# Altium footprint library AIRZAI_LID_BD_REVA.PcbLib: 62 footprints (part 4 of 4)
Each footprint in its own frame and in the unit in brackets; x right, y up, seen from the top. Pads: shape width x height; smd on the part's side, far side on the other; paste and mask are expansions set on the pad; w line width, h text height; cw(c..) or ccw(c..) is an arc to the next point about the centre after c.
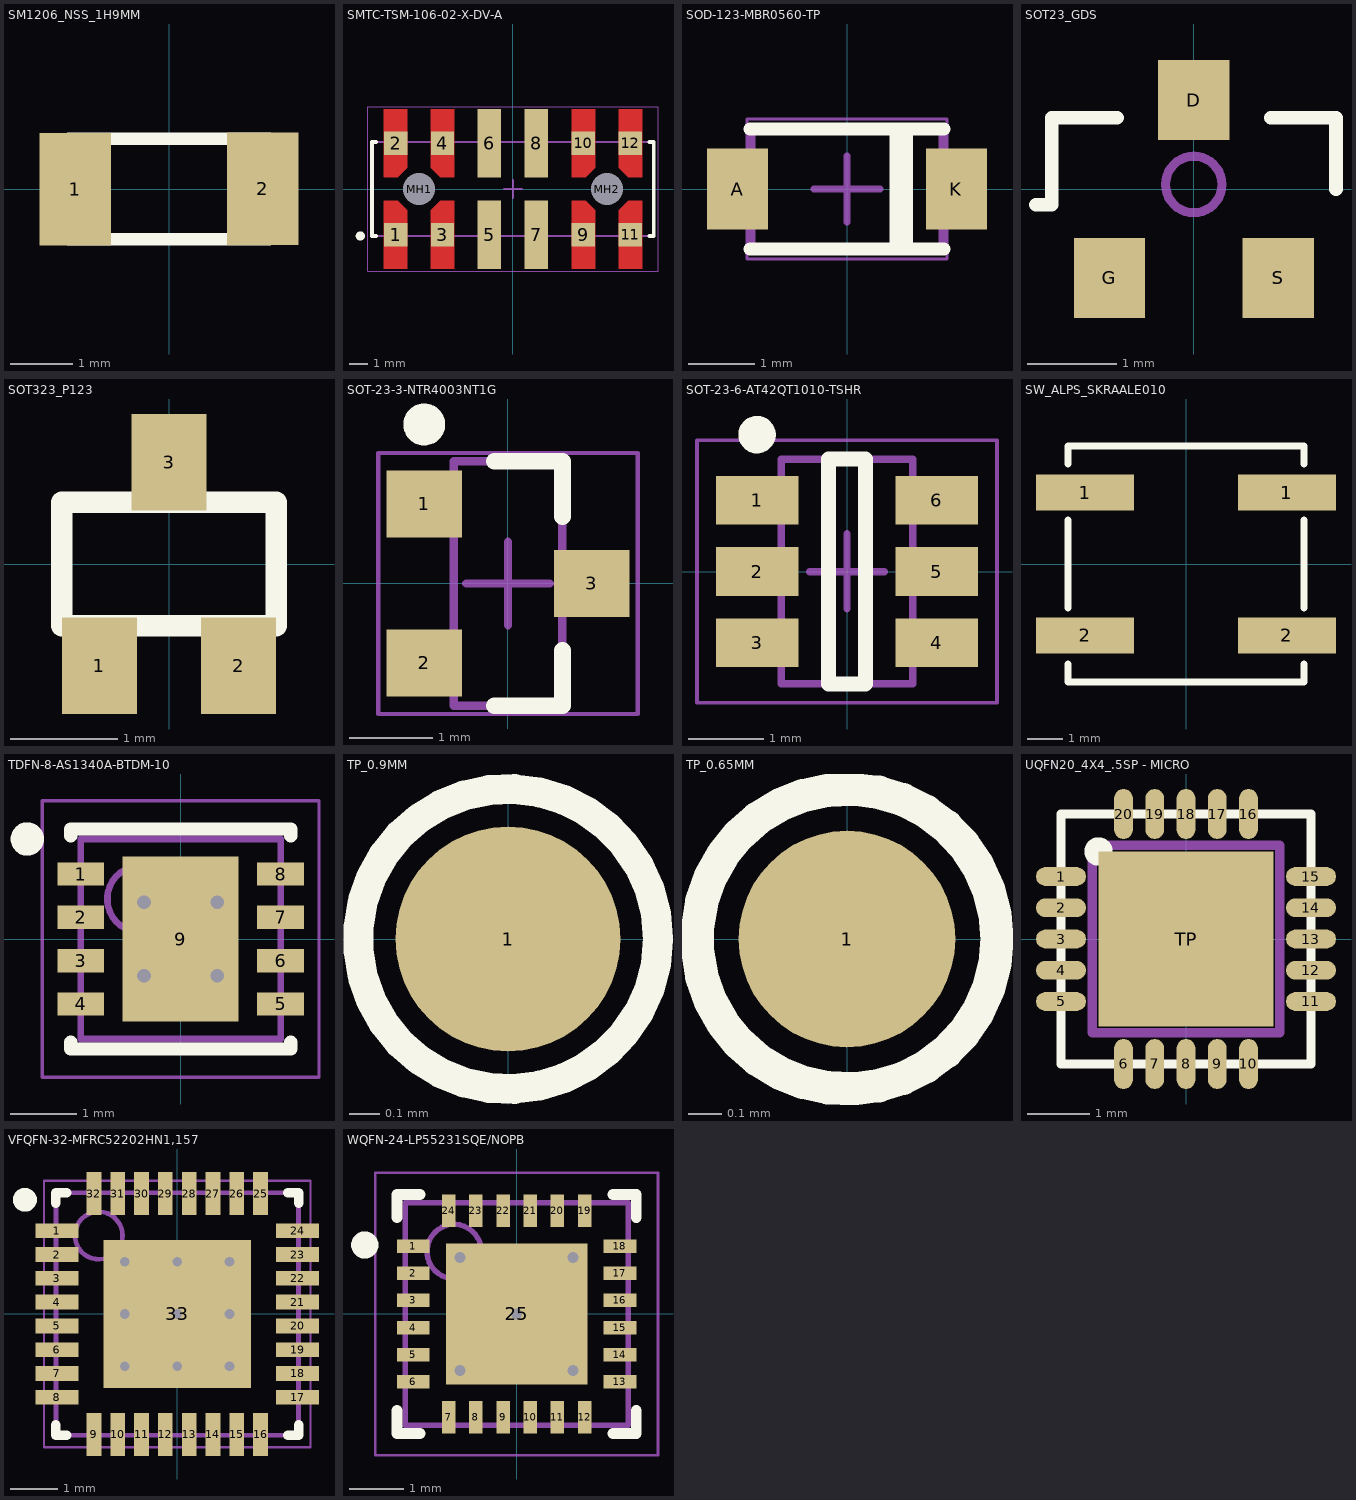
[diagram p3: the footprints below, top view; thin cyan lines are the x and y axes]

## SM1206_NSS_1H9MM [mm] "CAP_1206_1.9MM_HIGH"
height 1.9
pads (2):
  rect 1.15x1.8 smd: 1(-1.5,0) 2(1.5,0)
Top Overlay:
  lines w0.2: -1.6,-0.8 1.6,-0.8 1.6,0.8 -1.6,0.8 -1.6,-0.8
3D body: height 1.9, standoff 0, extent -1.7,-0.9 1.7,0.9

## SMTC-TSM-106-02-X-DV-A [mm] "Double Row Gullwing Asm, 2x6 Pins, Vertical, 2.54mm Pitch, Male"
height 12.19
pads (14):
  rect 1.27x1.27 smd: 1(-6.35,-2.475) 2(-6.35,2.475) 3(-3.81,-2.475) 4(-3.81,2.475) 9(3.81,-2.475) 10(3.81,2.475) 11(6.35,-2.475) 12(6.35,2.475)
  rect 1.27x3.68 smd: 5(-1.27,-2.475) 6(-1.27,2.475) 7(1.27,-2.475) 8(1.27,2.475)
  round 1.43 hole 1.73 unplated: MH1(-5.08,0) MH2(5.08,0)
Top Layer:
  region: -6.985,0.635 -6.225,0.635 -5.715,1.145 -5.715,4.315 -6.985,4.315
  region: -3.175,0.635 -3.935,0.635 -4.445,1.145 -4.445,4.315 -3.175,4.315
  region: 6.985,0.635 6.225,0.635 5.715,1.145 5.715,4.315 6.985,4.315
  region: 3.175,0.635 3.935,0.635 4.445,1.145 4.445,4.315 3.175,4.315
  region: 3.175,-0.635 3.935,-0.635 4.445,-1.145 4.445,-4.315 3.175,-4.315
  region: 6.985,-0.635 6.225,-0.635 5.715,-1.145 5.715,-4.315 6.985,-4.315
  region: -3.175,-0.635 -3.935,-0.635 -4.445,-1.145 -4.445,-4.315 -3.175,-4.315
  region: -6.985,-0.635 -6.225,-0.635 -5.715,-1.145 -5.715,-4.315 -6.985,-4.315
Top Overlay:
  circle w0.25: c-8.255,-2.54 r0.125
  lines w0.2: -7.385,-2.54 -7.62,-2.54 -7.62,2.54 -7.385,2.54 ; 7.385,-2.54 7.62,-2.54 7.62,2.54 7.385,2.54
Mechanical 13:
  lines w0.1: -7.62,-2.54 -7.62,2.54 7.62,2.54 7.62,-2.54 -7.62,-2.54
Mechanical 15:
  lines w0.05: -7.845,-4.44 -7.845,4.44 7.845,4.44 7.845,-4.44 -7.845,-4.44
  lines w0.1: -0.5,0 0.5,0 ; 0,-0.5 0,0.5
3D body "TSM-106-02-T-DV-A-TR.stp": height 11.94, standoff -1.27, extent -7.62,-3.721 7.62,3.721

## SOD-123-MBR0560-TP [mil] "SODFL, 2-Leads, Body 1.8x2.85mm, IPC Medium Density"
height 53.15
pads (2):
  rect 36x48.03 smd: A(-64.5,0) K(64.5,0)
Top Overlay:
  lines w7.8: 29,-35 29,35 ; 35,-35 35,34.43
  lines w7.87: -57.09,-35.43 57.09,-35.43 ; -57.09,35.43 57.09,35.43
Mechanical 13:
  lines w3.94: -56.1,-35.43 56.1,-35.43 56.1,35.43 -56.1,35.43 -56.1,-35.43
Mechanical 15:
  lines w1.97: -59.06,-41.34 59.06,-41.34 59.06,41.34 -59.06,41.34 -59.06,-41.34
  lines w3.94: -19.68,0 19.68,0 ; 0,-19.68 0,19.68
3D body "SW3DPS-SOD123-DEFAULT.STEP": height 52, standoff 2, extent -72.83,-31.49 72.84,31.51

## SOT23_GDS [mm]
height 1.2
pads (3):
  rect 0.8x0.9 smd: D(0,1)
  rect 0.8x0.9 smd paste-0.05 mask+0.07: G(-0.95,-1) S(0.95,-1)
Top Overlay:
  lines w0.152: -1.775,-0.175 -1.6,-0.175 -1.6,0.8 -0.864,0.8 ; 0.864,0.8 1.6,0.8 1.6,0
Mechanical 3:
  lines w0.102: -0.318,0.051 cw(c0,0.051) 0,0.368 cw(c0,0.051) 0.318,0.051 cw(c0,0.051) 0,-0.267 cw(c0,0.051) -0.318,0.051
3D body: height 1.2, standoff 0, extent -1.5,-0.7 1.5,0.7

## SOT323_P123 [mm] "123_PINS"
height 1
pads (3):
  rect 0.7x0.9 smd: 1(-0.65,-0.95) 2(0.65,-0.95) 3(0,0.95)
Top Overlay:
  lines w0.2: -1,-0.575 1,-0.575 1,0.575 -1,0.575 -1,-0.575
Mechanical 1:
  lines w0.127: -1,-0.6 -0.85,-0.6 1,-0.6 1,0.6 -1,0.6 -1,-0.6
3D body: height 0.1, standoff 0, extent 0.45,-1.1 0.85,-0.675
3D body: height 0.1, standoff 0, extent -0.85,-1.1 -0.45,-0.675
3D body: height 0.1, standoff 0, extent -0.2,0.675 0.2,1.1
3D body: height 1.1, standoff 0.1, extent -1.1,-0.675 1.1,0.675

## SOT-23-3-NTR4003NT1G [mm] "SOT23, 3-Leads, Body 2.92x1.3mm, Pitch 0.95mm"
height 1.11
pads (3):
  rect 0.9x0.8 smd: 1(-1,0.95) 2(-1,-0.95) 3(1,0)
Top Overlay:
  circle w0.25: c-1,1.9 r0.125
  lines w0.2: -0.165,-1.46 0.65,-1.46 0.65,-0.8 ; -0.165,1.46 0.65,1.46 0.65,0.8
Mechanical 13:
  lines w0.1: -0.65,-1.46 -0.65,1.46 0.65,1.46 0.65,-1.46 -0.65,-1.46
Mechanical 15:
  lines w0.05: -1.55,-1.56 -1.55,1.56 1.55,1.56 1.55,-1.56 -1.55,-1.56
  lines w0.1: -0.5,0 0.5,0 ; 0,-0.5 0,0.5
3D body: height 1.11, standoff 0.01, extent -0.65,-1.46 0.65,1.46

## SOT-23-6-AT42QT1010-TSHR [mm] "SOT23, 6-Leads, Body 2.9x1.6mm, Pitch 0.95mm, Lead Span 2.8mm, IPC Medium Density"
height 1.45
pads (6):
  rect 1.1x0.65 smd: 1(-1.2,0.95) 2(-1.2,0) 3(-1.2,-0.95) 4(1.2,-0.95) 5(1.2,0) 6(1.2,0.95)
Top Overlay:
  circle w0.25: c-1.2,1.825 r0.125
  lines w0.2: -0.25,-1.5 0.25,-1.5 0.25,1.5 -0.25,1.5 -0.25,-1.5
Mechanical 13:
  lines w0.1: -0.875,-1.5 -0.875,1.5 0.875,1.5 0.875,-1.5 -0.875,-1.5
Mechanical 15:
  lines w0.05: -2,-1.75 -2,1.75 2,1.75 2,-1.75 -2,-1.75
  lines w0.1: -0.5,0 0.5,0 ; 0,-0.5 0,0.5
3D body: height 1.45, standoff 0, extent -0.875,-1.5 0.875,1.5

## SW_ALPS_SKRAALE010 [mm] "6.2MM SQ 2.9RD ACT"
height 3.4
pads (4):
  rect 2.75x1 smd paste-0.1 mask+0.102: 1(-2.825,2) 1(2.825,2) 2(-2.825,-2) 2(2.825,-2)
Top Overlay:
  lines w0.198: -3.3,-2.8 -3.3,-3.3 3.3,-3.3 3.3,-2.8 ; -3.3,-1.233 -3.3,1.232 ; -3.3,2.8 -3.3,3.3 3.3,3.3 3.3,2.8 ; 3.3,-1.233 3.3,1.232
3D body "SKRAAL.STEP": height 3.48, standoff 0, extent -3.399,-3.215 3.399,3.215

## TDFN-8-AS1340A-BTDM-10 [mm]
height 0.8
pads (9):
  rect 0.7x0.35 smd: 1(-1.498,0.975) 2(-1.498,0.325) 3(-1.498,-0.325) 4(-1.498,-0.975) 5(1.498,-0.975) 6(1.498,-0.325) 7(1.498,0.325) 8(1.498,0.975)
  rect 1.74x2.48 smd: 9(0,0)
via -0.55,0.55 diameter 0.508 hole 0.203
via 0.55,0.55 diameter 0.508 hole 0.203
via -0.55,-0.55 diameter 0.508 hole 0.203
via 0.55,-0.55 diameter 0.508 hole 0.203
Top Overlay:
  circle w0.25: c-2.3,1.5 r0.125
  lines w0.2: -1.65,-1.55 -1.65,-1.65 0.25,-1.65 1.65,-1.65 1.65,-1.55 ; -1.65,1.55 -1.65,1.65 0.25,1.65 1.65,1.65 1.65,1.55
Mechanical 13:
  circle w0.1: c-0.6,0.6 r0.5
  lines w0.1: -1.5,-1.5 -1.5,1.5 1.5,1.5 1.5,-1.5 -1.5,-1.5
Mechanical 15:
  lines w0.05: -2.075,-2.075 -2.075,2.075 2.075,2.075 2.075,-2.075 -2.075,-2.075
  lines w0.1: -0.5,0 0.5,0 ; 0,-0.5 0,0.5
3D body "TDFN-8-AS1340A-BTDM-10.step": height 0.8, standoff 0, extent -1.51,-1.5 1.51,1.5

## TP_0.9MM [mm] "0.9MM DIA TESTPOINT"
height 7
pads (1):
  round 0.75 smd paste-5 mask+0.05: 1(0,0)
Top Overlay:
  circle w0.1: c0,0 r0.5

## TP_0.65MM [mm] "0.65MM DIA TESTPOINT"
height 7
pads (1):
  round 0.65 smd paste-5 mask+0.05: 1(0,0)
Top Overlay:
  circle w0.1: c0,0 r0.45

## UQFN20_4X4_.5SP - MICRO [mm]
height 0.5
pads (21):
  rrect100% 0.8x0.3 smd paste-0.025 mask+0.05: 1(-2,1) 2(-2,0.5) 3(-2,0) 4(-2,-0.5) 5(-2,-1) 11(2,-1) 12(2,-0.5) 13(2,0) 14(2,0.5) 15(2,1)
  rrect100% 0.3x0.8 smd paste-0.025 mask+0.05: 6(-1,-2) 7(-0.5,-2) 8(0,-2) 9(0.5,-2) 10(1,-2) 16(1,2) 17(0.5,2) 18(0,2) 19(-0.5,2) 20(-1,2)
  rect 2.8x2.8 smd paste-5 mask+0.05: TP(0,0)
Top Overlay:
  circle w0.254: c-1.4,1.4 r0.1
  lines w0.15: -2,-2 -2,2 2,2 2,-2 -2,-2
Top Paste:
  region: 1.194,-0.508 1.202,-0.527 1.202,-1.077 1.194,-1.096 1.175,-1.104 0.625,-1.104 0.606,-1.096 0.598,-1.077 0.598,-0.527 0.606,-0.508 0.625,-0.5 1.175,-0.5
  region: 1.192,0.294 1.2,0.275 1.2,-0.275 1.192,-0.294 1.173,-0.302 0.623,-0.302 0.604,-0.294 0.596,-0.275 0.596,0.275 0.604,0.294 0.623,0.302 1.173,0.302
  region: 1.194,1.096 1.202,1.077 1.202,0.527 1.194,0.508 1.175,0.5 0.625,0.5 0.606,0.508 0.598,0.527 0.598,1.077 0.606,1.096 0.625,1.104 1.175,1.104
  region: 0.294,-0.508 0.302,-0.527 0.302,-1.077 0.294,-1.096 0.275,-1.104 -0.275,-1.104 -0.294,-1.096 -0.302,-1.077 -0.302,-0.527 -0.294,-0.508 -0.275,-0.5 0.275,-0.5
  region: 0.292,0.294 0.3,0.275 0.3,-0.275 0.292,-0.294 0.273,-0.302 -0.277,-0.302 -0.296,-0.294 -0.304,-0.275 -0.304,0.275 -0.296,0.294 -0.277,0.302 0.273,0.302
  region: 0.294,1.096 0.302,1.077 0.302,0.527 0.294,0.508 0.275,0.5 -0.275,0.5 -0.294,0.508 -0.302,0.527 -0.302,1.077 -0.294,1.096 -0.275,1.104 0.275,1.104
  region: -0.606,1.096 -0.598,1.077 -0.598,0.527 -0.606,0.508 -0.625,0.5 -1.175,0.5 -1.194,0.508 -1.202,0.527 -1.202,1.077 -1.194,1.096 -1.175,1.104 -0.625,1.104
  region: -0.608,0.294 -0.6,0.275 -0.6,-0.275 -0.608,-0.294 -0.627,-0.302 -1.177,-0.302 -1.196,-0.294 -1.204,-0.275 -1.204,0.275 -1.196,0.294 -1.177,0.302 -0.627,0.302
  region: -0.606,-0.508 -0.598,-0.527 -0.598,-1.077 -0.606,-1.096 -0.625,-1.104 -1.175,-1.104 -1.194,-1.096 -1.202,-1.077 -1.202,-0.527 -1.194,-0.508 -1.175,-0.5 -0.625,-0.5
Mechanical 1:
  circle w0.15: c-0.85,-0.85 r0.206
  lines w0.15: -1.5,-1.5 -1.5,1.5 1.5,1.5 1.5,-1.5 -1.5,-1.5
  text ".Designator" at -1.1,-0.325 h0.48
3D body: height 0.5, standoff 0, extent -2,-2 2,2

## VFQFN-32-MFRC52202HN1,157 [mm]
height 1
pads (33):
  rect 0.9x0.31 smd: 1(-2.529,1.75) 2(-2.529,1.25) 3(-2.529,0.75) 4(-2.529,0.25) 5(-2.529,-0.25) 6(-2.529,-0.75) 7(-2.529,-1.25) 8(-2.529,-1.75) 17(2.529,-1.75) 18(2.529,-1.25) 19(2.529,-0.75) 20(2.529,-0.25) 21(2.529,0.25) 22(2.529,0.75) 23(2.529,1.25) 24(2.529,1.75)
  rect 0.31x0.9 smd: 9(-1.75,-2.529) 10(-1.25,-2.529) 11(-0.75,-2.529) 12(-0.25,-2.529) 13(0.25,-2.529) 14(0.75,-2.529) 15(1.25,-2.529) 16(1.75,-2.529) 25(1.75,2.529) 26(1.25,2.529) 27(0.75,2.529) 28(0.25,2.529) 29(-0.25,2.529) 30(-0.75,2.529) 31(-1.25,2.529) 32(-1.75,2.529)
  rect 3.1x3.1 smd: 33(0,0)
via -1.1,1.1 diameter 0.5 hole 0.203
via 0,1.1 diameter 0.5 hole 0.203
via 1.1,1.1 diameter 0.5 hole 0.203
via -1.1,0 diameter 0.5 hole 0.203
via 0,0 diameter 0.5 hole 0.203
via 1.1,0 diameter 0.5 hole 0.203
via -1.1,-1.1 diameter 0.5 hole 0.203
via 0,-1.1 diameter 0.5 hole 0.203
via 1.1,-1.1 diameter 0.5 hole 0.203
Top Overlay:
  circle w0.25: c-3.2,2.4 r0.125
  lines w0.2: -2.55,-2.325 -2.55,-2.55 -2.325,-2.55 ; -2.55,2.325 -2.55,2.55 -2.325,2.55 ; 2.325,-2.55 2.55,-2.55 2.55,-2.325 ; 2.325,2.55 2.55,2.55 2.55,2.325
Top Assembly:
  circle w0.1: c-1.65,1.65 r0.5
  lines w0.1: -2.55,-2.55 -2.55,2.55 2.55,2.55 2.55,-2.55 -2.55,-2.55
Top Courtyard:
  lines w0.05: -2.8,-2.8 -2.8,2.8 2.8,2.8 2.8,-2.8 -2.8,-2.8
  lines w0.1: -0.5,0 0.5,0 ; 0,-0.5 0,0.5
3D body "VFQFN-32-MFRC52202HN1,157.step": height 1, standoff 0, extent -2.55,-2.55 2.55,2.55

## WQFN-24-LP55231SQE/NOPB [mm] "QFN, 24-Leads, Body 3.97x3.97mm, Pitch 0.50mm, Thermal Pad 2.60x2.60mm, IPC Medium Density"
height 0.8
pads (25):
  rect 0.6x0.25 smd: 1(-1.9,1.25) 2(-1.9,0.75) 3(-1.9,0.25) 4(-1.9,-0.25) 5(-1.9,-0.75) 6(-1.9,-1.25) 13(1.9,-1.25) 14(1.9,-0.75) 15(1.9,-0.25) 16(1.9,0.25) 17(1.9,0.75) 18(1.9,1.25)
  rect 0.25x0.6 smd: 7(-1.25,-1.9) 8(-0.75,-1.9) 9(-0.25,-1.9) 10(0.25,-1.9) 11(0.75,-1.9) 12(1.25,-1.9) 19(1.25,1.9) 20(0.75,1.9) 21(0.25,1.9) 22(-0.25,1.9) 23(-0.75,1.9) 24(-1.25,1.9)
  rect 2.6x2.6 smd: 25(0,0)
via 0,0 diameter 0.508 hole 0.203
via -1.04,1.04 diameter 0.508 hole 0.203
via 1.04,1.04 diameter 0.508 hole 0.203
via -1.04,-1.04 diameter 0.508 hole 0.203
via 1.04,-1.04 diameter 0.508 hole 0.203
Top Overlay:
  circle w0.25: c-2.794,1.27 r0.125
  lines w0.2: -2.2,-1.775 -2.2,-2.2 -1.775,-2.2 ; -2.2,1.775 -2.2,2.2 -1.775,2.2 ; 1.775,-2.2 2.2,-2.2 2.2,-1.775 ; 1.775,2.2 2.2,2.2 2.2,1.775
Mechanical 13:
  circle w0.1: c-1.15,1.15 r0.5
  lines w0.1: -2.05,-2.05 -2.05,2.05 2.05,2.05 2.05,-2.05 -2.05,-2.05
Mechanical 15:
  lines w0.05: -2.6,-2.6 -2.6,2.6 2.6,2.6 2.6,-2.6 -2.6,-2.6
  lines w0.1: -0.5,0 0.5,0 ; 0,-0.5 0,0.5
3D body "User Library-WQFN-24.STEP": height 0.8, standoff 0, extent -2.01,-2.01 2.01,2.01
